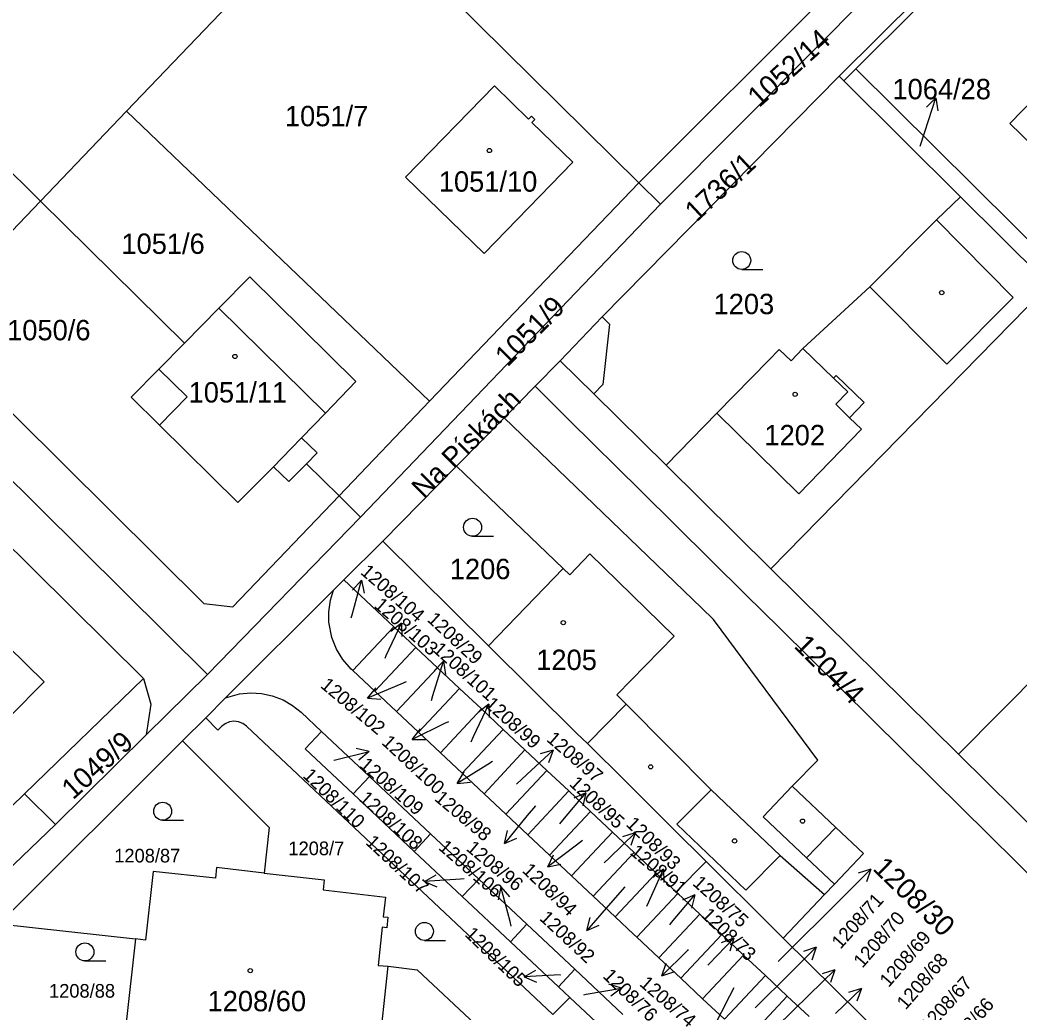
# Model space of a CAD drawing. Extents: x -724107 to -720612, y -1045267 to -1038441.
# Drawn here: x -722081.2 to -721997.8, y -1043740.8 to -1043658 of the extents above; entities that cross this region are included whole.
import ezdxf

# ---------------------------------------------------------------- set-up
doc = ezdxf.new("R2010")
doc.units = 0
for name, color, linetype in [('Hranice parcel', 7, 'Continuous'), ('Parcelní čísla', 7, 'Continuous'), ('Pop  PČ popisy', 7, 'Continuous'), ('Vnitřní kresba', 7, 'Continuous'), ('Značky budov', 7, 'Continuous'), ('Značky kultur', 7, 'Continuous')]:
    doc.layers.add(name, color=color, linetype=linetype)

msp = doc.modelspace()

# ---------------------------------------------------------------- linework, layer by layer
at = {"layer": 'Hranice parcel'}
for p, q in [((-722065.58, -1043712.63), (-722184.76, -1043594.54)), ((-722012.9, -1043662.71), (-721989.7, -1043639.56)), ((-722072.35, -1043665.62), (-722054.48, -1043646.97)), ((-722029.61, -1043671.6), (-722006.7, -1043648.69)), ((-722048.44, -1043652.95), (-722029.61, -1043671.6)), ((-722012.51, -1043663.09), (-722011.5, -1043662.08)), ((-722012.51, -1043663.09), (-722012.9, -1043662.71)), ((-722002.79, -1043672.76), (-722012.51, -1043663.09)), ((-722079.53, -1043673.13), (-722072.35, -1043665.62)), ((-722047.07, -1043689.83), (-722072.35, -1043665.62)), ((-722079.53, -1043673.13), (-722085.67, -1043667.07)), ((-722047.07, -1043689.83), (-722029.61, -1043671.6)), ((-722027.82, -1043673.38), (-722029.61, -1043671.6)), ((-722089.38, -1043683.42), (-722079.53, -1043673.13)), ((-722067.52, -1043684.99), (-722079.53, -1043673.13)), ((-722027.82, -1043673.38), (-722052.83, -1043699.49)), ((-721995.4, -1043680.11), (-722002.79, -1043672.76)), ((-722018.61, -1043703.8), (-721995.4, -1043680.11)), ((-722036.17, -1043686.44), (-722038.27, -1043688.58)), ((-722038.27, -1043688.58), (-722040.85, -1043691.2)), ((-722070.94, -1043712.95), (-722094.18, -1043689.93)), ((-722054.62, -1043697.72), (-722047.07, -1043689.83)), ((-722040.85, -1043691.2), (-722044.81, -1043695.23)), ((-722054.62, -1043697.72), (-722057.34, -1043695.04)), ((-722044.81, -1043695.23), (-722050.98, -1043701.51)), ((-722027.34, -1043695.16), (-722018.61, -1043703.8)), ((-722002.96, -1043719.28), (-721979.65, -1043695.76)), ((-722052.83, -1043699.49), (-722054.62, -1043697.72)), ((-722052.83, -1043699.49), (-722065.58, -1043712.63)), ((-722054.22, -1043704.73), (-722050.98, -1043701.51)), ((-722050.98, -1043701.51), (-722042.15, -1043710.23)), ((-722018.61, -1043703.8), (-722002.96, -1043719.28)), ((-722055.07, -1043705.58), (-722054.22, -1043704.73)), ((-722054.22, -1043704.73), (-722050.04, -1043708.65)), ((-722050.04, -1043708.65), (-722053.46, -1043712.3)), ((-722050.04, -1043708.65), (-722048.22, -1043710.37)), ((-722048.22, -1043710.37), (-722051.64, -1043714.01)), ((-722048.22, -1043710.37), (-722046.4, -1043712.08)), ((-722070.71, -1043717.67), (-722065.58, -1043712.63)), ((-722051.64, -1043714.01), (-722053.46, -1043712.3)), ((-722046.4, -1043712.08), (-722049.82, -1043715.72)), ((-722046.4, -1043712.08), (-722044.58, -1043713.79)), ((-722080.85, -1043722.58), (-722070.94, -1043712.95)), ((-722049.82, -1043715.72), (-722051.64, -1043714.01)), ((-722044.58, -1043713.79), (-722047.99, -1043717.43)), ((-722044.58, -1043713.79), (-722042.75, -1043715.5)), ((-722065.74, -1043716.23), (-722064.08, -1043714.57)), ((-722047.99, -1043717.43), (-722049.82, -1043715.72)), ((-722042.75, -1043715.5), (-722046.17, -1043719.15)), ((-722042.75, -1043715.5), (-722040.93, -1043717.21)), ((-722065.74, -1043716.23), (-722067.68, -1043718.16)), ((-722078.28, -1043725.13), (-722070.71, -1043717.67)), ((-722036.78, -1043740.98), (-722062.34, -1043716.94)), ((-722056.09, -1043717.37), (-722052.08, -1043721.14)), ((-722046.17, -1043719.15), (-722047.99, -1043717.43)), ((-722040.93, -1043717.21), (-722044.35, -1043720.86)), ((-722040.93, -1043717.21), (-722039.11, -1043718.92)), ((-722083, -1043733.43), (-722067.68, -1043718.16)), ((-722044.35, -1043720.86), (-722046.17, -1043719.15)), ((-722039.11, -1043718.92), (-722042.52, -1043722.57)), ((-722039.11, -1043718.92), (-722037.29, -1043720.63)), ((-721991.37, -1043730.73), (-722002.96, -1043719.28)), ((-722042.52, -1043722.57), (-722044.35, -1043720.86)), ((-722037.29, -1043720.63), (-722040.7, -1043724.28)), ((-722037.29, -1043720.63), (-722035.46, -1043722.34)), ((-722052.08, -1043721.14), (-722053.45, -1043722.59)), ((-722052.08, -1043721.14), (-722046.98, -1043725.93)), ((-722093.54, -1043734.91), (-722080.85, -1043722.58)), ((-722078.28, -1043725.13), (-722080.85, -1043722.58)), ((-722053.45, -1043722.59), (-722048.35, -1043727.39)), ((-722040.7, -1043724.28), (-722042.52, -1043722.57)), ((-722035.46, -1043722.34), (-722038.88, -1043725.99)), ((-722035.46, -1043722.34), (-722033.64, -1043724.06)), ((-722038.88, -1043725.99), (-722040.7, -1043724.28)), ((-722033.64, -1043724.06), (-722037.06, -1043727.7)), ((-722033.64, -1043724.06), (-722031.82, -1043725.77)), ((-722091.03, -1043737.39), (-722078.28, -1043725.13)), ((-722046.98, -1043725.93), (-722048.35, -1043727.39)), ((-722046.98, -1043725.93), (-722042.97, -1043729.69)), ((-722037.06, -1043727.7), (-722038.88, -1043725.99)), ((-722031.82, -1043725.77), (-722035.23, -1043729.41)), ((-722031.82, -1043725.77), (-722029.99, -1043727.48)), ((-722048.35, -1043727.39), (-722044.34, -1043731.15)), ((-722029.99, -1043727.48), (-722033.41, -1043731.12)), ((-722029.99, -1043727.48), (-722028.17, -1043729.19)), ((-722035.23, -1043729.41), (-722037.06, -1043727.7)), ((-722026.51, -1043730.75), (-722024, -1043728.24)), ((-722028.17, -1043729.19), (-722031.59, -1043732.84)), ((-722028.17, -1043729.19), (-722026.51, -1043730.75)), ((-722042.97, -1043729.69), (-722044.34, -1043731.15)), ((-722042.97, -1043729.69), (-722038.96, -1043733.46)), ((-722033.41, -1043731.12), (-722035.23, -1043729.41)), ((-722026.35, -1043730.9), (-722029.77, -1043734.55)), ((-722026.51, -1043730.75), (-722026.35, -1043730.9)), ((-722026.35, -1043730.9), (-722024.52, -1043732.61)), ((-722044.34, -1043731.15), (-722040.33, -1043734.92)), ((-722031.59, -1043732.84), (-722033.41, -1043731.12)), ((-722024.52, -1043732.61), (-722027.94, -1043736.26)), ((-722024.52, -1043732.61), (-722022.7, -1043734.33)), ((-722083, -1043733.43), (-722071.61, -1043734.69)), ((-722038.96, -1043733.46), (-722040.33, -1043734.92)), ((-722038.96, -1043733.46), (-722034.95, -1043737.22)), ((-722022.7, -1043734.33), (-722026.12, -1043737.97)), ((-722022.7, -1043734.33), (-722020.88, -1043736.04)), ((-722040.33, -1043734.92), (-722036.32, -1043738.68)), ((-722027.94, -1043736.26), (-722029.77, -1043734.55)), ((-722026.12, -1043737.97), (-722027.94, -1043736.26)), ((-722020.88, -1043736.04), (-722024.3, -1043739.68)), ((-722020.88, -1043736.04), (-722019.05, -1043737.75)), ((-722034.95, -1043737.22), (-722036.32, -1043738.68)), ((-722024.3, -1043739.68), (-722026.12, -1043737.97)), ((-722019.05, -1043737.75), (-722022.47, -1043741.39)), ((-722019.05, -1043737.75), (-722017.23, -1043739.46)), ((-722036.32, -1043738.68), (-722035.37, -1043739.57)), ((-722035.37, -1043739.57), (-722036.78, -1043740.98)), ((-722032.31, -1043742.44), (-722035.37, -1043739.57)), ((-722022.47, -1043741.39), (-722024.3, -1043739.68)), ((-722017.23, -1043739.46), (-722020.65, -1043743.1)), ((-722017.23, -1043739.46), (-722015.41, -1043741.17))]:
    msp.add_line(p, q, dxfattribs=at)
for points in [[(-721992.58, -1043643.95), (-721996.48, -1043647.1), (-722011.5, -1043662.08)], [(-722004.97, -1043650.39), (-722014.45, -1043659.97), (-722027.82, -1043673.38)], [(-721983.42, -1043673.17), (-721985.46, -1043675.26), (-721986.84, -1043673.91), (-721988.96, -1043676.07), (-721998.67, -1043666.64), (-721985.15, -1043652.75), (-721979.7, -1043658.08), (-721978.8, -1043657.18), (-721968.74, -1043666.96), (-721978.97, -1043677.48), (-721983.42, -1043673.17)], [(-722011.5, -1043662.08), (-721991.75, -1043681.7), (-721992.75, -1043682.75)], [(-722012.9, -1043662.71), (-722032.67, -1043682.78), (-722036.17, -1043686.44)], [(-722038.83, -1043666.28), (-722038.58, -1043666.03), (-722038.3, -1043666.31), (-722038.54, -1043666.56), (-722035.13, -1043669.87), (-722042.52, -1043677.51), (-722049.07, -1043671.12), (-722041.66, -1043663.52), (-722038.83, -1043666.28)], [(-722002.79, -1043672.76), (-722004.77, -1043674.69), (-722010.35, -1043680.27), (-722015.92, -1043685.41), (-722016.92, -1043686.45), (-722017.9, -1043685.5), (-722018.78, -1043686.4), (-722023.1, -1043690.82), (-722027.34, -1043695.16)], [(-722067.52, -1043684.99), (-722064.64, -1043682.07), (-722062.06, -1043679.45), (-722053.21, -1043688.18), (-722055.76, -1043690.82), (-722057.74, -1043692.87), (-722056.44, -1043694.12), (-722057.34, -1043695.04)], [(-722089.38, -1043683.42), (-722065.9, -1043706.69), (-722063.49, -1043706.98), (-722054.62, -1043697.72)], [(-722057.34, -1043695.04), (-722058.8, -1043696.52), (-722060.09, -1043695.3), (-722063.06, -1043698.26), (-722069.6, -1043691.81), (-722071.96, -1043689.49), (-722069.64, -1043687.14), (-722067.52, -1043684.99)], [(-722036.17, -1043686.44), (-722033.37, -1043689.21), (-722027.34, -1043695.16)], [(-722038.27, -1043688.58), (-722035.43, -1043691.39), (-722029.44, -1043697.31), (-722020.71, -1043705.95), (-722017.86, -1043708.76), (-722005.07, -1043721.41), (-721993.47, -1043732.88)], [(-722017.56, -1043734.62), (-722014.12, -1043730.98), (-722013.3, -1043730.12), (-722010.88, -1043727.55), (-722013.17, -1043725.38), (-722016.81, -1043721.94), (-722014.68, -1043719.78), (-722023.39, -1043708.03), (-722024.38, -1043707.07), (-722040.85, -1043691.2)], [(-722044.81, -1043695.23), (-722035.93, -1043703.79), (-722042.15, -1043710.23)], [(-722064.08, -1043714.57), (-722055.22, -1043705.73), (-722055.07, -1043705.58)], [(-722053.46, -1043712.3), (-722053.6, -1043712.17), (-722054.3, -1043711.38), (-722054.84, -1043710.52), (-722055.23, -1043709.55), (-722055.47, -1043708.25), (-722055.48, -1043707.39), (-722055.33, -1043706.43), (-722055.07, -1043705.58)], [(-722082.26, -1043710.25), (-722079.23, -1043713.24)], [(-722042.15, -1043710.23), (-722034.78, -1043717.56), (-722033.89, -1043718.38), (-722030.64, -1043721.61), (-722026.78, -1043725.48), (-722024, -1043728.24)], [(-722079.23, -1043713.24), (-722082.09, -1043716.13)], [(-722070.94, -1043712.95), (-722070.31, -1043715.1), (-722070.71, -1043717.67)], [(-722064.08, -1043714.57), (-722062.91, -1043714.24), (-722061.98, -1043714.15), (-722061.1, -1043714.21), (-722060.19, -1043714.4), (-722059.28, -1043714.75), (-722058.51, -1043715.2), (-722057.79, -1043715.78), (-722056.09, -1043717.37)], [(-722064.43, -1043716.97), (-722064.72, -1043717.26), (-722065.74, -1043716.23)], [(-722062.34, -1043716.94), (-722062.653, -1043716.712), (-722063.014, -1043716.573), (-722063.384, -1043716.53), (-722063.767, -1043716.583), (-722064.124, -1043716.733), (-722064.43, -1043716.97)], [(-722056.09, -1043717.37), (-722057.46, -1043718.83), (-722053.45, -1043722.59)], [(-722067.68, -1043718.16), (-722060.46, -1043725.4), (-722060.88, -1043729.19)], [(-722024, -1043728.24), (-722018.57, -1043733.61), (-722017.56, -1043734.62)], [(-722060.88, -1043729.19), (-722064.84, -1043728.74), (-722064.92, -1043729.63), (-722070.12, -1043729.06), (-722070.76, -1043734.8), (-722071.61, -1043734.69)], [(-722060.88, -1043729.19), (-722055.86, -1043729.76), (-722055.95, -1043730.6), (-722050.75, -1043731.21), (-722050.93, -1043732.85), (-722050.55, -1043732.88), (-722050.64, -1043733.75), (-722051.02, -1043733.71), (-722051.37, -1043736.9), (-722050.52, -1043736.97)], [(-722029.77, -1043734.55), (-722030.05, -1043734.28), (-722031.59, -1043732.84)], [(-722071.61, -1043734.69), (-722072.44, -1043742.15), (-722071.56, -1043742.23), (-722071.7, -1043743.42)], [(-722017.56, -1043734.62), (-722002.37, -1043749.65), (-721996.99, -1043754.98)], [(-722050.52, -1043736.97), (-722048.09, -1043737.27), (-722041.08, -1043743.85), (-722053.45, -1043756.18), (-722058.68, -1043755.61)], [(-722058.13, -1043750.36), (-722058.02, -1043749.49), (-722052.81, -1043750.07), (-722052.18, -1043744.38), (-722051.33, -1043744.46), (-722050.52, -1043736.97)], [(-722034.95, -1043737.22), (-722033.95, -1043738.16), (-722030.94, -1043740.99)]]:
    msp.add_lwpolyline(points, dxfattribs=at)
at = {"layer": 'Pop  PČ popisy'}
for p, q in [((-722005.76, -1043667.35), (-722004.833, -1043664.496)), ((-722004.833, -1043664.496), (-722005.618, -1043665.294)), ((-722004.833, -1043664.496), (-722004.666, -1043665.603)), ((-722006.14, -1043668.54), (-722005.76, -1043667.35)), ((-722053.53, -1043707.65), (-722052.753, -1043704.751)), ((-722052.753, -1043704.751), (-722053.496, -1043705.589)), ((-722052.753, -1043704.751), (-722052.529, -1043705.848)), ((-722053.6, -1043707.9), (-722053.53, -1043707.65)), ((-722050.69, -1043711.05), (-722049.422, -1043708.33)), ((-722049.422, -1043708.33), (-722050.299, -1043709.026)), ((-722049.422, -1043708.33), (-722049.391, -1043709.449)), ((-722050.78, -1043711.26), (-722050.69, -1043711.05)), ((-722046.79, -1043714.38), (-722045.913, -1043711.51)), ((-722045.913, -1043711.51), (-722046.684, -1043712.321)), ((-722045.913, -1043711.51), (-722045.727, -1043712.614)), ((-722049.48, -1043713.43), (-722052.242, -1043714.603)), ((-722049.02, -1043713.24), (-722049.48, -1043713.43)), ((-722052.242, -1043714.603), (-722051.516, -1043713.75)), ((-722052.242, -1043714.603), (-722051.125, -1043714.672)), ((-722046.92, -1043714.79), (-722046.79, -1043714.38)), ((-722043.4, -1043717.81), (-722042.132, -1043715.09)), ((-722042.132, -1043715.09), (-722043.009, -1043715.786)), ((-722042.132, -1043715.09), (-722042.101, -1043716.209)), ((-722045.82, -1043716.72), (-722048.517, -1043718.036)), ((-722045.49, -1043716.56), (-722045.82, -1043716.72)), ((-722048.517, -1043718.036), (-722047.837, -1043717.146)), ((-722048.517, -1043718.036), (-722047.398, -1043718.047)), ((-722043.6, -1043718.24), (-722043.4, -1043717.81)), ((-722055.02, -1043719.77), (-722052.108, -1043719.044)), ((-722052.108, -1043719.044), (-722053.201, -1043718.8)), ((-722052.108, -1043719.044), (-722052.959, -1043719.772)), ((-722038.96, -1043720.98), (-722036.765, -1043718.933)), ((-722036.765, -1043718.933), (-722037.839, -1043719.25)), ((-722036.765, -1043718.933), (-722037.156, -1043719.983)), ((-722055.06, -1043719.78), (-722055.02, -1043719.77)), ((-722042.22, -1043720.12), (-722044.765, -1043721.71)), ((-722041.83, -1043719.88), (-722042.22, -1043720.12)), ((-722044.765, -1043721.71), (-722044.181, -1043720.755)), ((-722039.82, -1043721.77), (-722038.96, -1043720.98)), ((-722044.765, -1043721.71), (-722043.65, -1043721.604)), ((-722035.95, -1043724.79), (-722034.021, -1043722.491)), ((-722034.021, -1043722.491), (-722035.048, -1043722.936)), ((-722034.021, -1043722.491), (-722034.281, -1043723.58)), ((-722038.24, -1043723.58), (-722038.92, -1043724.4)), ((-722038.92, -1043724.4), (-722040.809, -1043726.732)), ((-722036.2, -1043725.09), (-722035.95, -1043724.79)), ((-722040.809, -1043726.732), (-722040.567, -1043725.639)), ((-722032.07, -1043727.92), (-722029.911, -1043725.835)), ((-722029.911, -1043725.835), (-722030.98, -1043726.171)), ((-722029.911, -1043725.835), (-722030.284, -1043726.891)), ((-722040.809, -1043726.732), (-722039.789, -1043726.269)), ((-722034.31, -1043726.48), (-722034.82, -1043726.86)), ((-722034.82, -1043726.86), (-722037.217, -1043728.666)), ((-722037.217, -1043728.666), (-722036.718, -1043727.663)), ((-722037.217, -1043728.666), (-722036.116, -1043728.463)), ((-722032.51, -1043728.33), (-722032.07, -1043727.92)), ((-722047.484, -1043729.909), (-722046.52, -1043729.34)), ((-722028.79, -1043731.6), (-722027.569, -1043728.858)), ((-722027.569, -1043728.858), (-722028.434, -1043729.57)), ((-722027.569, -1043728.858), (-722027.519, -1043729.977)), ((-722012.38, -1043730.98), (-722010.258, -1043728.858)), ((-722010.258, -1043728.858), (-722011.32, -1043729.212)), ((-722010.258, -1043728.858), (-722010.612, -1043729.92)), ((-722044.49, -1043729.7), (-722047.484, -1043729.909)), ((-722047.484, -1043729.909), (-722046.45, -1043730.339)), ((-722044.18, -1043729.68), (-722044.49, -1043729.7)), ((-722041.137, -1043730.331), (-722041.361, -1043731.428)), ((-722040.36, -1043733.23), (-722041.137, -1043730.331)), ((-722041.137, -1043730.331), (-722040.394, -1043731.169)), ((-722030.78, -1043730.35), (-722031.99, -1043731.71)), ((-722026.88, -1043733.32), (-722024.951, -1043731.021)), ((-722024.951, -1043731.021), (-722025.978, -1043731.466)), ((-722024.951, -1043731.021), (-722025.211, -1043732.11)), ((-722017.98, -1043736.57), (-722012.38, -1043730.98)), ((-722031.99, -1043731.71), (-722033.959, -1043733.975)), ((-722028.94, -1043731.94), (-722028.79, -1043731.6)), ((-722040.25, -1043733.61), (-722040.36, -1043733.23)), ((-722033.959, -1043733.975), (-722033.68, -1043732.891)), ((-722027.04, -1043733.51), (-722026.88, -1043733.32)), ((-722033.959, -1043733.975), (-722032.924, -1043733.548)), ((-722023.77, -1043736.79), (-722021.685, -1043734.631)), ((-722021.685, -1043734.631), (-722022.741, -1043735.004)), ((-722021.685, -1043734.631), (-722022.021, -1043735.7)), ((-722025.56, -1043735.65), (-722027.682, -1043737.772)), ((-722025.5, -1043735.58), (-722025.56, -1043735.65)), ((-722016.95, -1043737.51), (-722014.828, -1043735.388)), ((-722014.828, -1043735.388), (-722015.89, -1043735.742)), ((-722014.828, -1043735.388), (-722015.182, -1043736.45)), ((-722027.682, -1043737.772), (-722027.328, -1043736.71)), ((-722023.85, -1043736.87), (-722023.77, -1043736.79)), ((-722039.167, -1043737.837), (-722038.193, -1043737.285)), ((-722036.17, -1043737.68), (-722039.167, -1043737.837)), ((-722036.17, -1043737.68), (-722036.16, -1043737.68)), ((-722027.682, -1043737.772), (-722026.62, -1043737.418)), ((-722019.9, -1043740.43), (-722016.95, -1043737.51)), ((-722015.41, -1043739.35), (-722013.251, -1043737.265)), ((-722013.251, -1043737.265), (-722014.32, -1043737.601)), ((-722013.251, -1043737.265), (-722013.624, -1043738.321)), ((-722039.167, -1043737.837), (-722038.141, -1043738.285)), ((-722031.055, -1043738.789), (-722032.128, -1043738.47)), ((-722034.19, -1043739.35), (-722034.01, -1043739.31)), ((-722034.01, -1043739.31), (-722031.055, -1043738.789)), ((-722031.055, -1043738.789), (-722031.954, -1043739.456)), ((-722021.69, -1043738.76), (-722022.04, -1043739.47)), ((-722018.17, -1043742.05), (-722015.41, -1043739.35)), ((-722013.21, -1043740.9), (-722011.051, -1043738.815)), ((-722011.051, -1043738.815), (-722012.12, -1043739.151)), ((-722011.051, -1043738.815), (-722011.424, -1043739.871)), ((-722022.04, -1043739.47), (-722023.402, -1043742.144))]:
    msp.add_line(p, q, dxfattribs=at)
at = {"layer": 'Vnitřní kresba'}
for p, q in [((-721998.39, -1043681.18), (-722004.77, -1043674.69)), ((-722003.92, -1043686.74), (-722010.35, -1043680.27)), ((-722003.92, -1043686.74), (-721998.39, -1043681.18)), ((-722064.64, -1043682.07), (-722055.76, -1043690.82)), ((-722032.67, -1043682.78), (-722032.06, -1043683.38)), ((-722032.06, -1043683.38), (-722032.62, -1043688.42)), ((-722015.92, -1043685.41), (-722013.38, -1043687.91)), ((-722069.64, -1043687.14), (-722067.29, -1043689.46)), ((-722032.62, -1043688.42), (-722033.37, -1043689.21)), ((-722013.15, -1043687.67), (-722013.38, -1043687.91)), ((-722012.18, -1043689.04), (-722013.38, -1043687.91)), ((-722010.81, -1043689.94), (-722013.15, -1043687.67)), ((-722012.18, -1043689.04), (-722013.19, -1043690.07)), ((-722067.29, -1043689.46), (-722069.6, -1043691.81)), ((-722013.19, -1043690.07), (-722012.03, -1043691.2)), ((-722012.03, -1043691.2), (-722010.81, -1043689.94)), ((-722023.1, -1043690.82), (-722016.28, -1043697.56)), ((-722011.04, -1043692.16), (-722012.03, -1043691.2)), ((-722011.04, -1043692.16), (-722016.28, -1043697.56)), ((-722058.61, -1043693.78), (-722057.74, -1043692.87)), ((-722058.61, -1043693.78), (-722060.09, -1043695.3)), ((-722035.38, -1043704.32), (-722033.7, -1043702.57)), ((-722033.7, -1043702.57), (-722026.67, -1043709.42)), ((-722035.93, -1043703.79), (-722035.38, -1043704.32)), ((-722026.67, -1043709.42), (-722031.45, -1043714.32)), ((-722030.67, -1043715.11), (-722031.45, -1043714.32)), ((-722030.67, -1043715.11), (-722033.89, -1043718.38)), ((-722023.59, -1043722.25), (-722030.67, -1043715.11)), ((-722023.59, -1043722.25), (-722026.43, -1043725.12)), ((-722023.59, -1043722.25), (-722017.83, -1043727.73)), ((-722019.23, -1043724.5), (-722016.81, -1043721.94)), ((-722020.69, -1043730.62), (-722026.43, -1043725.12)), ((-722019.23, -1043724.5), (-722015.62, -1043727.92)), ((-722015.62, -1043727.92), (-722013.17, -1043725.38)), ((-722017.83, -1043727.73), (-722020.69, -1043730.62)), ((-722017.83, -1043727.73), (-722014.12, -1043730.98)), ((-722013.3, -1043730.12), (-722015.62, -1043727.92))]:
    msp.add_line(p, q, dxfattribs=at)
at = {"layer": 'Značky budov'}
for centre in [(-722042.077, -1043668.909), (-722004.347, -1043680.769), (-722063.307, -1043686.089), (-722016.577, -1043689.249), (-722035.917, -1043708.299), (-722028.627, -1043720.329), (-722015.957, -1043724.859), (-722021.627, -1043726.509), (-722062.027, -1043737.339)]:
    msp.add_circle(centre, 0.175, dxfattribs=at)
at = {"layer": 'Značky kultur'}
for p, q in [((-722021.033, -1043678.83), (-722019.283, -1043678.83)), ((-722043.483, -1043701.09), (-722041.733, -1043701.09)), ((-722069.333, -1043724.78), (-722067.583, -1043724.78)), ((-722047.503, -1043734.81), (-722045.753, -1043734.81)), ((-722075.823, -1043736.52), (-722074.073, -1043736.52))]:
    msp.add_line(p, q, dxfattribs=at)
for centre in [(-722021.033, -1043678.08), (-722043.483, -1043700.34), (-722069.333, -1043724.03), (-722047.503, -1043734.06), (-722075.823, -1043735.77)]:
    msp.add_circle(centre, 0.75, dxfattribs=at)

# ---------------------------------------------------------------- texts
at = {"layer": 'Parcelní čísla'}
for s, height, rotation, p in [('1052/14', 1.7, 42, (-722019.591, -1043665.381)), ('1736/1', 1.7, 43, (-722024.8, -1043674.921)), ('1051/9', 1.7, 45, (-722040.576, -1043687.018)), ('1208/104', 1.139, 319, (-722052.903, -1043704.178)), ('1208/103', 1.139, 319, (-722051.773, -1043706.958)), ('1208/29', 1.139, 317, (-722047.339, -1043708.122)), ('1208/101', 1.139, 318, (-722046.867, -1043710.653)), ('1204/4', 1.7, 315, (-722016.751, -1043710.321)), ('1208/102', 1.139, 320, (-722056.249, -1043713.644)), ('1208/99', 1.139, 318, (-722042.532, -1043715.222)), ('1049/9', 1.7, 42, (-722076.811, -1043723.131)), ('1208/97', 1.139, 319, (-722037.384, -1043718.122)), ('1208/100', 1.139, 317, (-722051.129, -1043718.379)), ('1208/109', 1.139, 319, (-722052.983, -1043720.288)), ('1208/110', 1.139, 316, (-722057.711, -1043721.135)), ('1208/95', 1.139, 317, (-722035.489, -1043721.822)), ('1208/108', 1.139, 318, (-722053.017, -1043723.083)), ('1208/98', 1.139, 320, (-722046.735, -1043723.073)), ('1208/93', 1.139, 316, (-722030.755, -1043725.183)), ('1208/107', 1.139, 317, (-722052.469, -1043726.719)), ('1208/106', 1.139, 319, (-722046.403, -1043727.158)), ('1208/96', 1.139, 320, (-722044.085, -1043727.243)), ('1208/91', 1.139, 320, (-722030.435, -1043727.563)), ('1208/94', 1.139, 316, (-722039.415, -1043729.053)), ('1208/30', 1.7, 316, (-722010.181, -1043728.895)), ('1208/75', 1.139, 318, (-722025.202, -1043730.132)), ('1208/71', 1.139, 48, (-722012.797, -1043735.602)), ('1208/92', 1.139, 317, (-722037.969, -1043733.042)), ('1208/73', 1.139, 316, (-722024.475, -1043732.783)), ('1208/70', 1.139, 49, (-722010.957, -1043737.174)), ('1208/105', 1.139, 316, (-722044.201, -1043734.375)), ('1208/69', 1.139, 49, (-722008.777, -1043738.794)), ('1208/68', 1.139, 49, (-722007.347, -1043740.654)), ('1208/76', 1.139, 316, (-722032.685, -1043737.853)), ('1208/74', 1.139, 319, (-722029.624, -1043738.532)), ('1208/67', 1.139, 48, (-722005.407, -1043742.542)), ('1208/66', 1.139, 49, (-722003.517, -1043744.364))]:
    msp.add_text(s, height=height, rotation=rotation, dxfattribs=at).set_placement(p)
for s, height, p in [('1064/28', 1.7, (-722008.458, -1043664.63)), ('1051/7', 1.7, (-722059.135, -1043666.88)), ('1051/10', 1.7, (-722046.298, -1043672.34)), ('1051/6', 1.7, (-722072.775, -1043677.53)), ('1203', 1.7, (-722023.38, -1043682.56)), ('1050/6', 1.7, (-722082.305, -1043684.74)), ('1051/11', 1.7, (-722067.168, -1043689.93)), ('1202', 1.7, (-722019.14, -1043693.5)), ('1206', 1.7, (-722045.38, -1043704.67)), ('1205', 1.7, (-722038.17, -1043712.25)), ('1208/7', 1.139, (-722058.844, -1043727.699)), ('1208/87', 1.139, (-722073.37, -1043728.309)), ('1208/88', 1.139, (-722078.81, -1043739.589)), ('1208/60', 1.7, (-722065.588, -1043740.72))]:
    msp.add_text(s, height=height, dxfattribs=at).set_placement(p)
at = {"layer": 'Pop  PČ popisy'}
msp.add_text('Na Pískách', height=1.7, rotation=45, dxfattribs=at).set_placement((-722047.538, -1043698.031))

doc.saveas('drawing.dxf')
